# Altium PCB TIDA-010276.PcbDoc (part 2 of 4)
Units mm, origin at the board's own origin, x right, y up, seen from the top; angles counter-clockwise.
Board outline 146.48 x 90.27 mm, 4 copper layers (Top Layer, Signal Layer1, Signal Layer2, Bottom Layer), stack 1.631 mm thick; 271 components, 98 nets, 671 pads, 1828 vias.
Unrouted connection lines stored in the file: 2.
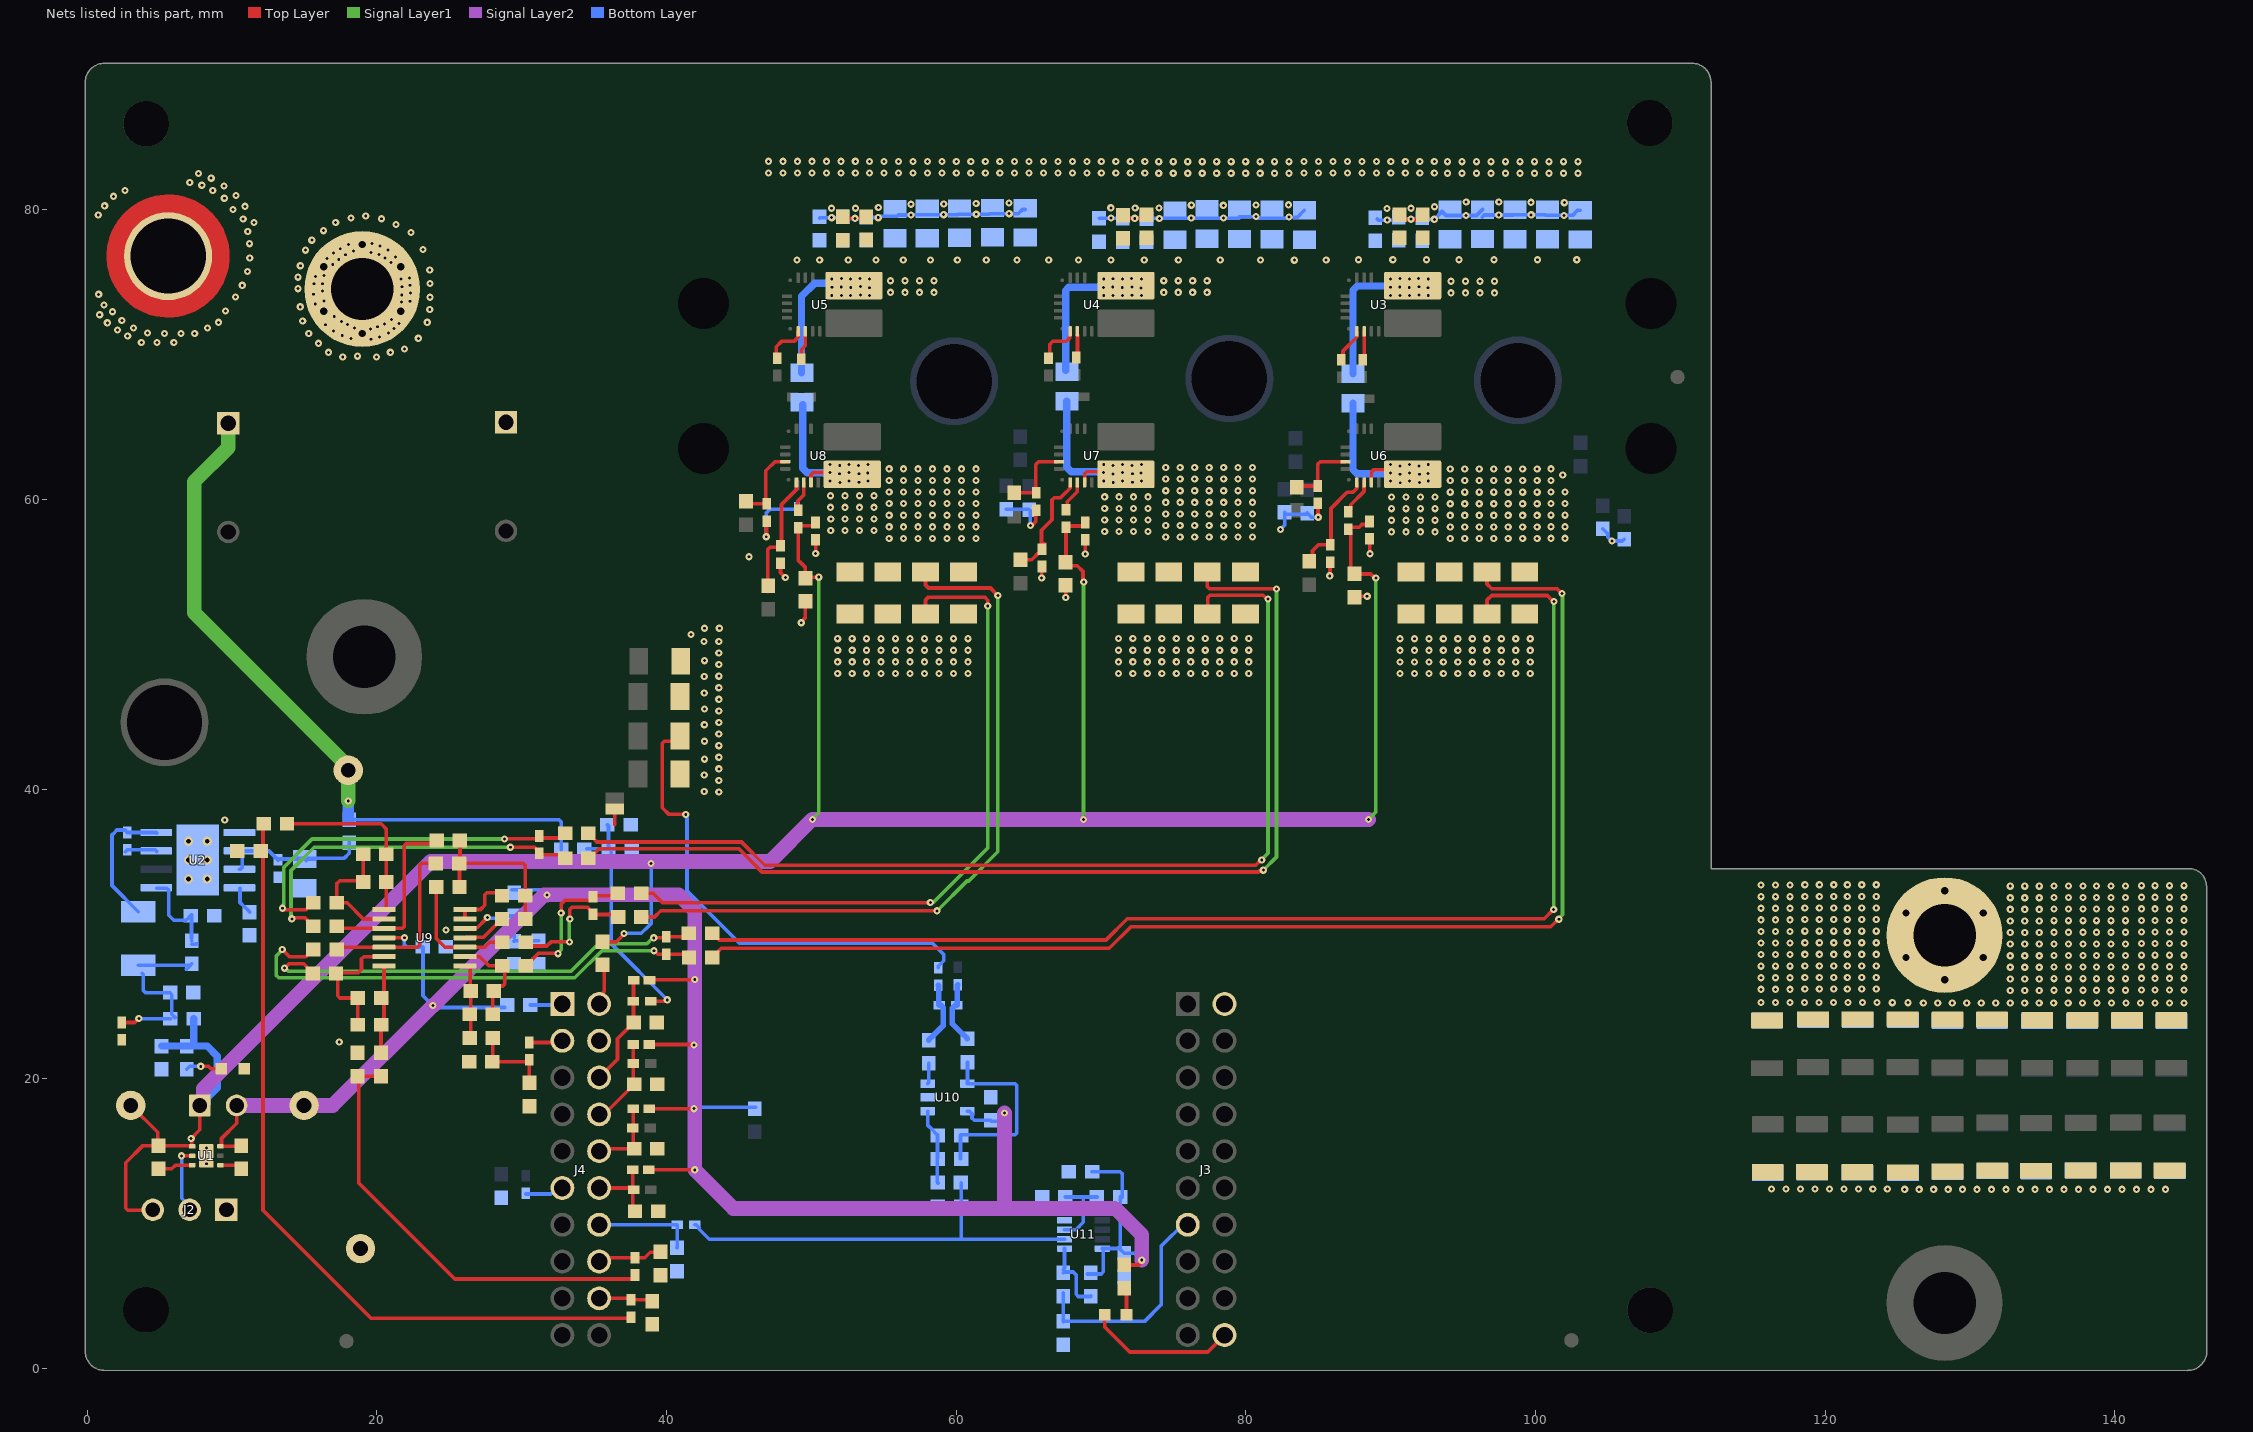
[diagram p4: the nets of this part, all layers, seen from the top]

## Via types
v1: diameter 0.5, hole 0.2, Top Layer to Bottom Layer, tented both sides, 1031 vias
v2: diameter 0.5, hole 0.2, Top Layer to Bottom Layer, 766 vias
v3: diameter 1, hole 0.5, Top Layer to Bottom Layer, 24 vias
v4: diameter 0.63, hole 0.33, Top Layer to Bottom Layer, tented both sides, 6 vias
v5: diameter 1.2, hole 0.8, Top Layer to Bottom Layer, 1 vias

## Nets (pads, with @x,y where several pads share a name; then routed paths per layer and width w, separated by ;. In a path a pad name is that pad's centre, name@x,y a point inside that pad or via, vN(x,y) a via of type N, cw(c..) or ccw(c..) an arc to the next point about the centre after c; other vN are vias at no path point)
"1.65V or 2.5V": C121.1 R46.2 R57.2 R63.2 R79.2 | length 11.3
  Top Layer w0.254: R63.2@25.715,33.294 R57.2@25.715,34.792 ; R57.2@25.732,34.884 25.747,34.899 R46.2@25.747,36.467 ; R57.2@25.77,34.847 25.807,34.884 30.102,34.884 30.251,34.735 R79.2@30.251,32.639 C121.1@30.251,31.042
"3.3V or 5V": C45.1 C104.2 C105.2 C112.2 C114.1 D2.1 D3.1 D4.1 D5.1 J1.2 R58.2 R65.2 R66.2 R78.2 R82.2 R92.1 TP1.1 U1.6 U9.4 U10.5 U11.8 | length 153.2
  Top Layer w0.254: U1.6@9.213,15.34 U1.6@9.265,15.34 ; J1.2@10.329,18.168 10.329,16.93 9.288,15.89 9.288,15.363 U1.6@9.265,15.34 ; C45.1@10.432,15.21 10.303,15.34 U1.6@9.265,15.34 ; U9.4@20.501,29.742 v1(21.911,29.742) ; D5.1@38.78,13.72 v1(41.957,13.72) ; D3.1@38.803,17.944 v1(41.907,17.944) ; D4.1@38.819,22.372 41.879,22.372 v1(41.907,22.345) ; D2.1@38.835,26.815 38.854,26.835 41.942,26.835 v1(41.961,26.854) ; R92.1@71.455,6.993 R92.1@71.617,7.156 72.593,7.156 72.701,7.263 72.701,7.293 72.824,7.416 v1(72.824,7.483)
  Signal Layer2 w0.254: v1(41.957,13.72) v1@41.961,13.725
  Signal Layer2 w1.016: J1.2@10.329,18.168 TP1.1@14.984,18.168 16.975,18.168 23.871,25.065 v1(23.876,25.065) 23.917,25.065 31.553,32.701 v1(31.753,32.701) 31.76,32.708 40.856,32.708 41.961,31.603 v1(41.961,26.854) v1@41.961,13.725 ; v1(41.957,13.72) 44.622,11.055 63.343,11.055 ; v1(63.343,17.64) 63.343,11.055 ; v1(72.824,7.483) 72.824,9.23 70.999,11.055 63.343,11.055
  Bottom Layer w0.254: v1(21.911,29.742) 21.911,29.241 22.06,29.092 23.135,29.092 C104.2@23.167,29.124 23.195,29.096 23.195,25.747 v1(23.876,25.065) ; v1@24.076,24.934 R82.2@28.85,24.934 ; R78.2@29.32,33.055 31.477,33.055 v1@31.626,32.907 ; v1(41.907,17.944) 41.973,17.944 42.066,18.038 R58.2@46.159,18.038 ; 44.383,18.04 R58.2@46.095,18.04 ; U10.5@60.786,17.774 60.928,17.774 61.101,17.601 61.101,17.289 61.25,17.14 C105.2@62.387,17.14 62.451,17.076 63.194,17.076 63.343,17.225 v1(63.343,17.64) ; R66.2@69.061,6.528 70.019,6.528 70.168,6.677 70.168,8.209 U11.8@70.09,8.287 71.286,8.287 C112.2@71.327,8.246 ; C114.1@69.391,13.582 71.335,13.582 71.484,13.433 R65.2@71.484,11.846 ; R65.2@71.327,11.846 C112.2@71.327,8.246 ; v1(72.824,7.483) 72.351,7.956 C112.2@71.617,7.956 C112.2@71.327,8.246
3V3Lauchpad: J4.1 R82.1 | length 2.2
  Bottom Layer w0.254: R82.1@30.616,25.099 32.745,25.099 J4.1@32.817,25.171
5V: C43.1 C44.1 C87.1 C88.1 C89.1 C90.1 C91.1 C92.1 J1.1 J2.3 R2.1 R4.2 R13.1 R14.1 R15.1 R81.1 TP3.1 U1.1 | length 193.1
  Top Layer w0.254: TP3.1@3.019,18.168 4.878,16.309 4.878,15.459 C44.1@4.943,15.395 ; J2.3@4.544,10.962 4.507,10.925 2.819,10.925 2.67,11.073 2.67,14.207 3.858,15.395 C44.1@4.943,15.395 ; J1.1@7.789,18.168 7.789,16.49 v1(7.188,15.89) 7.226,15.852 7.226,15.363 7.165,15.363 7.133,15.395 C44.1@4.943,15.395 ; R81.1@35.584,29.466 36.552,29.466 37.069,29.982 v1(37.069,30.046) ; C91.1@49.598,54.567 49.598,55.317 49.267,55.648 49.258,55.648 49.109,55.797 R15.1@49.109,58.063 49.24,58.194 50.129,58.194 50.302,58.367 C92.1@50.302,58.413 ; C91.1@49.682,54.642 v1(50.519,54.642) ; C87.1@67.558,55.682 67.808,55.432 68.361,55.432 68.767,55.027 68.767,54.36 v1(68.814,54.313) ; C87.1@67.571,55.668 67.591,55.688 R14.1@67.591,58.095 ; R14.1@67.663,58.175 C90.1@68.68,58.175 ; v1(68.793,37.917) 68.793,37.985 v1@68.853,38.046 ; C90.1@68.93,58.517 C90.1@69.103,58.69 ; C88.1@88.468,58.352 88.388,58.272 88.025,58.272 87.832,58.079 87.214,58.079 R13.1@87.08,57.944 87.245,57.779 87.245,55.14 87.53,54.855 88.637,54.855 88.918,54.575 v1(88.984,54.575)
  Signal Layer2 w1.016: J1.1@7.639,17.932 8.031,18.324 8.031,19.31 23.73,35.01 47.176,35.01 v1(50.083,37.917) v1(68.793,37.917) v1(88.471,37.917)
  Signal Layer1 w0.254: v1(50.083,37.917) 50.083,37.937 50.519,38.373 v1(50.519,54.642) ; v1(68.793,37.917) 68.803,37.927 68.803,54.303 v1(68.814,54.313) ; v1(88.471,37.917) 88.984,38.43 v1(88.984,54.575)
  Bottom Layer w0.254: C43.1@5.138,22.27 C43.1@5.141,22.267 ; v1@37.084,30.051 38.27,30.051 38.796,30.577 38.945,30.726 v1(38.945,34.879)
  Bottom Layer w0.508: C43.1@5.138,22.267 5.141,22.267 R4.2@6.891,22.267 R4.2@7.281,22.267 ; R2.1@7.36,24.155 7.36,22.346 R4.2@7.281,22.267 ; J1.1@7.789,18.168 9.003,19.382 9.003,21.565 8.301,22.267 R4.2@7.281,22.267
BAT+: C1.1 C2.1 C3.1 C4.1 C5.1 C6.1 C7.1 C8.1 C9.1 C10.1 C11.1 C12.1 C13.1 C14.1 C15.1 C16.1 C17.1 C18.1 C19.1 C20.1 C21.1 C22.1 C23.1 C24.1 C25.1 C26.1 C27.1 C28.1 C29.1 C30.1 C31.1 C32.1 C33.1 C34.1 C35.1 C36.1 C37.1 C38.1 C39.1 C40.2 C41.2 C42.2 C51.1 C52.1 C53.1 C54.1 C55.1 C56.1 C57.1 C58.1 C59.1 C60.1 C61.1 C62.1 C63.1 C64.1 C65.1 C66.1 C67.1 C68.1 C69.1 C70.1 C71.1 C72.1 C73.1 C74.1 C75.1 C76.1 C77.1 C78.1 C79.1 C80.1 C84.1 C85.1 C86.1 MHA1.1 MHA2.1 MP1.1 R1.2 R48.2 TP2.1 U3.7 U4.7 U5.7 | length 76.4
  Signal Layer1 w1: C1.1@9.751,65.261 9.751,64.994 9.743,64.986 9.743,64.165 9.743,63.589 7.398,61.244 7.398,52.194 18.034,41.557 TP2.1@18.034,41.308 v1(18.034,39.187)
  Bottom Layer w0.254: R1.2@18.575,37.892 32.589,37.892 32.738,37.743 R48.2@32.738,35.832 ; C2.1@28.79,65.83 28.79,65.509 C2.1@28.944,65.355 ; C86.1@67.568,68.911 C86.1@67.653,68.826 ; C3.1@143.806,13.631 C3.1@143.877,13.702
  Bottom Layer w0.508: C84.1@49.327,68.757 49.327,74.032 50.24,74.945 51.807,74.945 v2(52.072,74.681) ; C86.1@67.568,68.911 67.568,74.432 67.783,74.646 v2@70.181,74.646 ; 70.551,74.934 v2(70.815,74.67) ; C85.1@87.404,68.688 87.404,74.447 87.701,74.745 v2@90.773,74.745 ; 90.366,74.941 v2(90.631,74.677)
  Bottom Layer w0.8: v1(18.034,39.187) 18.034,38.674 18.035,38.672 18.035,37.97 R1.2@18.11,37.895
  other v1: 125.495,12.376 126.495,12.376 127.495,12.376 128.495,12.376 129.495,12.376 130.495,12.376 131.495,12.376 132.495,12.376 133.495,12.376 134.495,12.376 135.495,12.376 136.495,12.376 137.495,12.376 138.495,12.376 139.495,12.376 140.495,12.376 141.495,12.376 142.495,12.376 143.495,12.376 116.298,12.398 117.298,12.398 118.298,12.398 119.298,12.398 120.298,12.398 121.298,12.398 122.298,12.398 123.298,12.398 124.298,12.398 126.781,25.248 127.781,25.248 128.781,25.248 129.781,25.248 130.781,25.248 131.781,25.248 132.781,25.248 133.781,25.248 134.781,25.248 135.78,25.248 136.78,25.248 137.78,25.248 138.78,25.248 139.78,25.248 140.78,25.248 141.78,25.248 142.78,25.248 143.78,25.248 144.78,25.248 115.583,25.269 116.583,25.269 117.583,25.269 118.583,25.269 119.583,25.269 120.583,25.269 121.583,25.269 122.583,25.269 123.583,25.269 124.641,25.261 125.722,25.262 132.784,26.105 133.784,26.105 134.784,26.105 135.802,26.123 136.802,26.123 137.802,26.123 138.735,26.123 139.735,26.123 140.735,26.123 141.846,26.143 142.78,26.143 143.78,26.143 144.78,26.143 115.583,26.184 116.583,26.184 117.583,26.184 118.601,26.201 119.601,26.201 120.601,26.201 121.534,26.201 122.534,26.201 123.534,26.201 132.784,26.905 133.784,26.905 134.784,26.905 135.802,26.923 136.802,26.923 137.802,26.923 138.735,26.923 139.735,26.923 140.735,26.923 141.846,26.943 142.78,26.943 143.78,26.943 144.78,26.943 115.583,26.984 116.583,26.984 117.583,26.984 118.601,27.001 119.601,27.001 120.601,27.001 121.534,27.001 122.534,27.001 123.534,27.001 132.784,27.705 133.784,27.705 134.784,27.705 135.802,27.723 136.802,27.723 137.802,27.723 138.735,27.723 139.735,27.723 140.735,27.723 141.846,27.743 142.78,27.743 143.78,27.743 144.78,27.743 115.583,27.784 116.583,27.784 117.583,27.784 118.601,27.801 119.601,27.801 120.601,27.801 121.534,27.801 122.534,27.801 123.534,27.801 132.784,28.505 133.784,28.505 134.784,28.505 135.802,28.523 136.802,28.523 137.802,28.523 138.735,28.523 139.735,28.523 140.735,28.523 141.846,28.543 142.78,28.543 143.78,28.543 144.78,28.543 115.583,28.584 116.583,28.584 117.583,28.584 118.601,28.601 119.601,28.601 120.601,28.601 121.534,28.601 122.534,28.601 123.534,28.601 132.784,29.305 133.784,29.305 134.784,29.305 135.802,29.323 136.802,29.323 137.802,29.323 138.735,29.323 139.735,29.323 140.735,29.323 141.846,29.343 142.78,29.343 143.78,29.343 144.78,29.343 115.583,29.384 116.583,29.384 117.583,29.384 118.601,29.401 119.601,29.401 120.601,29.401 121.534,29.401 122.534,29.401 123.534,29.401 132.784,30.105 133.784,30.105 134.784,30.105 135.802,30.123 136.802,30.123 137.802,30.123 138.735,30.123 139.735,30.123 140.735,30.123 141.846,30.143 142.78,30.143 143.78,30.143 144.78,30.143 115.583,30.184 116.583,30.184 117.583,30.184 118.601,30.201 119.601,30.201 120.601,30.201 121.534,30.201 122.534,30.201 123.534,30.201 132.784,30.905 133.784,30.905 134.784,30.905 135.802,30.923 136.802,30.923 137.802,30.923 138.735,30.923 139.735,30.923 140.735,30.923 141.846,30.943 142.78,30.943 143.78,30.943 144.78,30.943 115.583,30.984 116.583,30.984 117.583,30.984 118.601,31.001 119.601,31.001 120.601,31.001 121.534,31.001 122.534,31.001 123.534,31.001 132.784,31.705 133.784,31.705 134.784,31.705 135.802,31.723 136.802,31.723 137.802,31.723 138.735,31.723 139.735,31.723 140.735,31.723 141.846,31.743 142.78,31.743 143.78,31.743 144.78,31.743 115.583,31.784 116.583,31.784 117.583,31.784 118.601,31.801 119.601,31.801 120.601,31.801 121.534,31.801 122.534,31.801 123.534,31.801 132.784,32.505 133.784,32.505 134.784,32.505 135.802,32.523 136.802,32.523 137.802,32.523 138.735,32.523 139.735,32.523 140.735,32.523 141.846,32.543 142.78,32.543 143.78,32.543 144.78,32.543 115.583,32.584 116.583,32.584 117.583,32.584 118.601,32.601 119.601,32.601 120.601,32.601 121.534,32.601 122.534,32.601 123.534,32.601 132.784,33.305 133.784,33.305 134.784,33.305 135.802,33.323 136.802,33.323 137.802,33.323 138.735,33.323 139.735,33.323 140.735,33.323 141.846,33.343 142.78,33.343 143.78,33.343 144.78,33.343 115.583,33.384 116.583,33.384 117.583,33.384 118.601,33.401 119.601,33.401 120.601,33.401 121.534,33.401 122.534,33.401 123.534,33.401 17.653,69.85 19.99,69.834 18.669,69.901 16.677,70.165 20.942,70.165 21.911,70.386 15.986,70.783 3.749,70.835 4.824,70.835 5.993,70.835 19.606,71.065 18.214,71.128 22.875,71.132 20.205,71.231 2.804,71.283 17.619,71.319 5.351,71.455 6.483,71.455 7.43,71.455 15.308,71.455 4.178,71.5 20.801,71.511 17.027,71.649 2.108,71.701 19.564,71.763 21.19,71.799 3.213,71.847 8.321,71.847 18.468,71.854 20.048,71.934 16.476,72.065 17.993,72.083 20.544,72.115 21.54,72.149 1.401,72.201 9.083,72.236 23.487,72.236 17.562,72.299 14.887,72.333 2.402,72.366 21.021,72.425 17.067,72.648 0.872,72.759 1.766,72.964 9.554,73.026 23.663,73.121 14.719,73.305 1.166,73.428 15.754,73.5 21.701,73.634 22.297,73.692 16.362,73.703 23.682,73.966 10.248,73.985 51.42,74.076 52.72,74.076 54.02,74.076 70.2,74.076 71.5,74.076 72.8,74.076 90,74.076 91.3,74.076 92.6,74.076 21.726,74.119 0.803,74.168 15.628,74.176 22.345,74.269 16.246,74.388 14.569,74.56 21.759,74.692 10.717,74.788 22.307,74.798 15.657,74.899 16.246,74.899 23.682,74.916 51.42,75.216 52.72,75.216 54.02,75.216 70.2,75.216 71.5,75.216 72.8,75.216 90,75.216 91.3,75.216 92.6,75.216 21.688,75.225 22.255,75.292 14.569,75.353 15.783,75.41 16.37,75.455 11.081,75.751 23.663,75.842 14.727,76.144 16.962,76.229 20.976,76.379 17.381,76.584 16.556,76.647 11.232,76.685 20.582,76.677 21.296,76.735 17.842,76.904 20.149,76.908 17.008,77.011 19.601,77.052 18.407,77.157 15.088,77.216 20.784,77.215 23.194,77.261 17.485,77.314 20.236,77.504 18.058,77.613 11.217,77.665 19.678,77.677 15.519,77.906 22.374,78.435 11.097,78.509 16.319,78.564 21.336,78.986 11.528,79.122 17.167,79.129 10.78,79.368 20.327,79.387 18.221,79.442 19.244,79.568 0.773,79.64 10.087,80.032 10.902,80.243 1.218,80.276 9.482,80.799 1.827,80.932 10.277,80.984 2.627,81.344 8.678,81.344 9.449,81.639 7.929,81.7 7.094,81.884 8.572,82.19 7.701,82.509
  other v2: 52.085,74.09 70.828,74.079 90.644,74.086 53.398,74.116 72.141,74.105 91.957,74.112 94.175,74.273 95.175,74.273 96.175,74.273 97.175,74.273 55.471,74.304 56.471,74.304 57.471,74.304 58.471,74.304 74.337,74.306 75.337,74.306 76.337,74.306 77.337,74.306 54.029,74.624 72.772,74.613 92.588,74.62 52.733,74.645 70.17,74.648 71.476,74.634 89.986,74.655 91.292,74.641 51.427,74.658 53.391,74.699 72.134,74.688 91.95,74.695 94.175,75.073 95.175,75.073 96.175,75.073 97.175,75.073 55.471,75.104 56.471,75.104 57.471,75.104 58.471,75.104 74.337,75.106 75.337,75.106 76.337,75.106 77.337,75.106 52.079,75.256 53.373,75.26 70.822,75.245 72.116,75.249 90.638,75.252 91.932,75.256 49.013,76.535 50.583,76.535 52.556,76.535 54.477,76.535 56.357,76.535 58.238,76.535 60.089,76.535 62.082,76.535 64.205,76.535 75.346,76.532 78.24,76.532 81.02,76.532 83.356,76.528 85.552,76.532 66.398,76.547 68.462,76.547 70.705,76.547 72.997,76.547 87.792,76.555 90.155,76.555 92.477,76.555 94.726,76.555 97.142,76.555 100.141,76.555 102.854,76.555 73.994,82.529 74.994,82.529 75.994,82.529 76.994,82.529 77.994,82.529 78.994,82.529 79.994,82.529 80.994,82.529 81.994,82.529 82.994,82.529 93.938,82.529 94.938,82.529 95.938,82.529 96.938,82.529 97.938,82.529 98.938,82.529 99.938,82.529 100.938,82.529 101.938,82.529 102.938,82.529 47.048,82.552 48.048,82.552 49.048,82.552 50.048,82.552 51.048,82.552 52.048,82.552 53.048,82.552 54.021,82.541 55.021,82.541 56.021,82.541 57.021,82.541 58.021,82.541 59.021,82.541 60.021,82.541 61.021,82.541 62.021,82.541 63.021,82.541 64.032,82.541 65.032,82.541 66.032,82.541 67.032,82.541 68.032,82.541 69.032,82.541 70.032,82.541 71.032,82.541 72.032,82.541 73.032,82.541 84.019,82.541 85.019,82.541 86.019,82.541 87.019,82.541 88.019,82.541 89.019,82.541 90.019,82.541 91.019,82.541 92.019,82.541 93.019,82.541 54.021,83.341 55.021,83.341 56.021,83.341 57.021,83.341 58.021,83.341 59.021,83.341 60.021,83.341 61.021,83.341 62.021,83.341 63.021,83.341 64.032,83.341 65.032,83.341 66.032,83.341 67.032,83.341 68.032,83.341 69.032,83.341 70.032,83.341 71.032,83.341 72.032,83.341 73.032,83.341 73.994,83.329 74.994,83.329 75.994,83.329 76.994,83.329 77.994,83.329 78.994,83.329 79.994,83.329 80.994,83.329 81.994,83.329 82.994,83.329 84.019,83.341 85.019,83.341 86.019,83.341 87.019,83.341 88.019,83.341 89.019,83.341 90.019,83.341 91.019,83.341 92.019,83.341 93.019,83.341 93.938,83.329 94.938,83.329 95.938,83.329 96.938,83.329 97.938,83.329 98.938,83.329 99.938,83.329 100.938,83.329 101.938,83.329 102.938,83.329 47.048,83.352 48.048,83.352 49.048,83.352 50.048,83.352 51.048,83.352 52.048,83.352 53.048,83.352
  other v3: 128.254,26.846 125.591,28.384 130.917,28.384 125.591,31.458 130.917,31.458 128.254,32.996 19.001,71.455 16.338,72.993 21.664,72.993 16.338,76.067 21.664,76.067 19.001,77.605
DCBUS: C107.1 R48.1 R52.2 R84.1 | length 16.6
  Top Layer w0.254: R84.1@38.925,25.365 39.902,25.365 39.994,25.458 v1(40.063,25.458)
  Bottom Layer w0.254: R48.1@34.509,35.9 36.003,35.9 36.185,35.9 36.203,35.882 36.203,29.318 v1(40.063,25.458) ; C107.1@35.934,37.546 36.003,37.477 R52.2@36.003,35.882
GaN_U_AGND: C51.2 C52.2 C53.2 C54.2 C55.2 C66.2 C69.2 C70.2 C71.2 C72.2 C85.2 R22.1 R25.2 R26.2 R27.2 R28.2 U6.4 U6.6 | length 115.1
  Top Layer w0.254: R22.1@43.161,28.384 43.186,28.384 43.534,28.732 43.534,28.757 43.791,29.014 70.583,29.014 72.078,30.509 101.061,30.509 101.574,31.023 v1(101.619,31.023) ; U6.4@88.675,61.187 88.675,61.899 88.824,62.048 U6.6@91.214,62.048 ; C69.2@90.624,79.34 90.63,79.333 C72.2@92.187,79.333 ; R25.2@96.656,54.593 96.656,54.172 96.991,53.837 101.496,53.837 v1(101.827,53.507)
  Signal Layer1 w0.254: v1(101.619,31.023) 101.619,31.089 101.869,31.34 101.869,53.465 v1(101.827,53.507)
  Bottom Layer w0.254: C71.2@89.073,79.364 89.146,79.291 v1(89.772,79.291) 90.557,79.291 90.63,79.364 92.186,79.364 92.202,79.348 v1(93.019,79.348) 93.556,79.885 93.834,79.607 95.929,79.607 C55.2@96.343,80.021 ; C55.2@96.337,79.502 96.337,79.513 96.463,79.64 98.452,79.64 98.47,79.657 v1(99.706,79.657) 100.675,79.657 100.714,79.617 102.561,79.617 102.927,79.984 C54.2@103.092,79.984
  Bottom Layer w0.508: C85.2@87.404,66.656 87.404,62.068 87.701,61.771 v2@89.99,61.771
  other v1: 90,61.287 91.3,61.287 92.6,61.287 90,62.427 91.3,62.427 92.6,62.427 91.409,79.36 95.204,79.607 101.973,79.617 97.468,79.64 89.745,80.095 91.416,80.112 93.039,80.218 101.997,80.495 99.7,80.521 95.218,80.539 97.472,80.539
  other v2: 94.121,57.308 95.121,57.308 96.121,57.308 97.121,57.308 98.121,57.308 99.121,57.308 100.121,57.308 101.085,57.32 102.041,57.32 90.062,57.769 91.062,57.769 92.062,57.769 93.062,57.769 94.121,58.108 95.121,58.108 96.121,58.108 97.121,58.108 98.121,58.108 99.121,58.108 100.121,58.108 101.085,58.12 102.041,58.12 90.062,58.569 91.062,58.569 92.062,58.569 93.062,58.569 94.121,58.908 95.121,58.908 96.121,58.908 97.121,58.908 98.121,58.908 99.121,58.908 100.121,58.908 101.085,58.92 102.041,58.92 90.062,59.369 91.062,59.369 92.062,59.369 93.062,59.369 94.121,59.708 95.121,59.708 96.121,59.708 97.121,59.708 98.121,59.708 99.121,59.708 100.121,59.708 101.085,59.72 102.041,59.72 90.062,60.169 91.062,60.169 92.062,60.169 93.062,60.169 94.121,60.508 95.121,60.508 96.121,60.508 97.121,60.508 98.121,60.508 99.121,60.508 100.121,60.508 101.085,60.52 102.041,60.52 90.665,61.156 91.993,61.166 94.121,61.308 95.121,61.308 96.121,61.308 97.121,61.308 98.121,61.308 99.121,61.308 100.121,61.308 101.085,61.32 101.884,61.697 90.651,61.747 91.986,61.749 92.591,61.811 89.989,61.845 91.295,61.832 94.121,62.108 95.121,62.108 96.121,62.108 97.121,62.108 98.121,62.108 99.121,62.108 100.121,62.108 101.085,62.12 91.968,62.31 90.658,62.323
GaN_V_AGND: C56.2 C57.2 C58.2 C59.2 C60.2 C67.2 C73.2 C74.2 C75.2 C76.2 C86.2 R23.1 R29.2 R30.2 R31.2 R32.2 U7.4 U7.6 | length 99.6
  Top Layer w0.254: R23.1@34.639,35.175 34.664,35.175 35.012,35.523 35.012,35.548 35.346,35.882 45.011,35.882 46.603,34.29 80.875,34.29 80.949,34.364 81.17,34.364 v1(81.217,34.411) ; U7.4@68.875,61.187 68.875,61.773 69.024,61.922 U7.6@71.54,61.922 ; C74.2@71.526,79.64 71.75,79.417 v1(72.337,79.417) ; C74.2@71.529,79.403 C74.2@71.532,79.405 ; v1@72.292,79.425 72.3,79.417 72.901,79.417 C73.2@73.157,79.672 ; R31.2@77.343,55.008 77.343,53.995 77.491,53.846 82.094,53.846 v1(82.121,53.819)
  Signal Layer1 w0.254: v1(81.217,34.411) 82.121,35.316 v1(82.121,53.819)
  Bottom Layer w0.254: C75.2@69.894,79.425 C60.2@79.557,79.425 ; C60.2@79.574,79.516 v1@80.7,79.516 ; v1@80.682,79.425 v1@82.946,79.425 ; v1@82.99,79.481 83.555,79.481 C59.2@84.048,79.974
  Bottom Layer w0.508: C86.2@67.653,66.794 67.653,62.219 67.951,61.922 69.755,61.922
  other v1: 70.2,61.287 71.5,61.287 72.8,61.287 70.2,62.427 71.5,62.427 72.8,62.427 74.033,79.41 70.69,79.445 76.24,79.438 78.461,79.445 82.99,79.508 80.7,79.536 70.688,80.141 72.367,80.12 74.011,80.134 78.453,80.311 76.242,80.325 80.713,80.333 82.952,80.347
  other v2: 74.474,57.409 75.474,57.409 76.474,57.409 77.474,57.409 78.474,57.409 79.474,57.409 80.474,57.409 70.258,57.789 71.258,57.789 72.258,57.789 73.258,57.789 74.474,58.209 75.474,58.209 76.474,58.209 77.474,58.209 78.474,58.209 79.474,58.209 80.474,58.209 70.258,58.589 71.258,58.589 72.258,58.589 73.258,58.589 74.474,59.009 75.474,59.009 76.474,59.009 77.474,59.009 78.474,59.009 79.474,59.009 80.474,59.009 70.258,59.389 71.258,59.389 72.258,59.389 73.258,59.389 74.474,59.809 75.474,59.809 76.474,59.809 77.474,59.809 78.474,59.809 79.474,59.809 80.474,59.809 70.258,60.189 71.258,60.189 72.258,60.189 73.258,60.189 74.474,60.609 75.474,60.609 76.474,60.609 77.474,60.609 78.474,60.609 79.474,60.609 80.474,60.609 70.855,61.186 72.184,61.196 74.474,61.409 75.474,61.409 76.474,61.409 77.474,61.409 78.474,61.409 79.474,61.409 80.474,61.409 70.842,61.776 72.176,61.778 72.782,61.841 70.18,61.875 71.486,61.861 74.474,62.209 75.474,62.209 76.474,62.209 77.474,62.209 78.474,62.209 79.474,62.209 80.474,62.209 70.849,62.352 72.159,62.34
GaN_W_AGND: C61.2 C62.2 C63.2 C64.2 C65.2 C68.2 C77.2 C78.2 C79.2 C80.2 C84.2 R24.1 R33.2 R34.2 R35.2 R36.2 U8.4 U8.6 | length 75.5
  Top Layer w0.254: R24.1@38.277,31.176 39.188,31.176 39.615,31.603 58.691,31.603 v1(58.693,31.605) ; U8.4@49.984,61.187 49.984,61.713 50.139,61.867 U8.6@51.314,61.867 ; C77.2@52.176,79.511 52.27,79.416 v1(53.029,79.416) 53.7,79.416 C78.2@53.807,79.524 ; R35.2@57.89,55.008 57.89,54.101 58.101,53.89 62.372,53.89 v1(62.884,53.378)
  Signal Layer1 w0.254: v1(58.693,31.605) 60.754,33.667 60.87,33.667 62.884,35.681 v1(62.884,53.378)
  Bottom Layer w0.254: C79.2@50.595,79.444 50.614,79.463 v1(51.41,79.463) 52.134,79.463 52.202,79.396 C68.2@53.794,79.396 ; C68.2@53.805,79.468 v1@54.627,79.468 ; v1@54.63,79.409 54.643,79.409 54.788,79.554 55.919,79.554 56.008,79.644 56.962,79.644 56.975,79.657 59.132,79.657 v1(59.145,79.67) 60.1,79.67 60.126,79.696 62.298,79.696 62.338,79.736 64.301,79.736 64.59,80.025 C65.2@64.755,80.025
  Bottom Layer w0.508: C84.2@49.417,66.545 49.417,62.167 49.722,61.862 v2@51.961,61.862
  other v1: 51.309,61.287 52.609,61.287 53.909,61.287 51.309,62.427 52.609,62.427 53.909,62.427 54.627,79.46 56.896,79.644 61.394,79.696 63.666,79.736 51.409,80.113 53.065,80.112 54.635,80.17 56.896,80.386 59.151,80.402 61.386,80.444 63.662,80.465
  other v2: 55.38,57.318 56.38,57.318 57.38,57.318 58.38,57.318 59.38,57.318 60.38,57.318 61.38,57.318 51.351,57.858 52.326,57.861 53.326,57.861 54.326,57.861 55.38,58.118 56.38,58.118 57.38,58.118 58.38,58.118 59.38,58.118 60.38,58.118 61.38,58.118 51.355,58.663 52.326,58.661 53.326,58.661 54.326,58.661 55.38,58.918 56.38,58.918 57.38,58.918 58.38,58.918 59.38,58.918 60.38,58.918 61.38,58.918 51.326,59.461 52.326,59.461 53.326,59.461 54.326,59.461 55.38,59.718 56.38,59.718 57.38,59.718 58.38,59.718 59.38,59.718 60.38,59.718 61.38,59.718 51.326,60.261 52.326,60.261 53.326,60.261 54.326,60.261 55.38,60.518 56.38,60.518 57.38,60.518 58.38,60.518 59.38,60.518 60.38,60.518 61.38,60.518 51.974,61.187 53.303,61.197 55.38,61.318 56.38,61.318 57.38,61.318 58.38,61.318 59.38,61.318 60.38,61.318 61.38,61.318 51.961,61.778 53.296,61.78 53.901,61.842 51.299,61.876 52.605,61.863 55.38,62.118 56.38,62.118 57.38,62.118 58.38,62.118 59.38,62.118 60.38,62.118 61.38,62.118 51.968,62.354 53.278,62.341
GND: C43.2 C44.2 C45.2 C47.2 C48.2 C49.2 C50.2 C87.2 C88.2 C89.2 C90.2 C91.2 C92.2 C93.2 C94.2 C95.2 C96.2 C97.2 C98.2 C104.1 C105.1 C106.2 C107.2 C109.2 C110.2 C112.1 C113.2 C114.2 C115.2 C117.2 C118.2 C119.2 C120.2 C121.2 C122.2 C123.2 C124.2 C125.2 C126.2 C127.2 C128.2 C129.2 C130.2 D1.1 J2.1 J3.2 J4.4 NT1.2 R5.1 R6.1 R52.1 R70.1 R75.1 R76.1 R77.1 R80.1 RT1.1 TP4.1 U1.3 U1.4 U1.7@8.238,14.69 U2.1 U2.9 U9.11 U10.2 U11.4 | length 33.5
  Top Layer w0.254: C44.2@4.943,13.795 5.855,13.795 6.1,14.04 U1.3@7.263,14.04 ; U1.4@9.213,14.04 10.404,14.04 C45.2@10.648,13.795 ; U9.11@26.101,29.742 26.149,29.79 27.399,29.79 28.278,30.669 28.278,30.694 28.626,31.042 C121.2@28.651,31.042 ; 36.437,37.549 36.443,37.555 NT1.2@36.443,38.632 ; C95.2@46.856,58.504 C95.2@46.889,58.471 ; v1(46.895,57.434) 46.911,57.45 46.911,58.488 C95.2@46.927,58.504 ; C98.2@47.879,55.597 47.879,54.95 v1(48.212,54.618) ; v1(49.309,51.495) 49.309,51.561 49.598,51.85 C91.2@49.598,52.967 ; C92.2@50.302,57.213 50.326,57.188 50.306,57.168 50.306,56.272 v1(50.309,56.269) ; v1(65.133,58.203) 65.18,58.25 65.274,58.25 65.51,58.486 65.51,59.241 C94.2@65.536,59.267 ; v1(65.91,54.589) 65.923,54.602 65.923,55.365 C97.2@65.935,55.378 ; C87.2@67.558,54.082 67.571,54.069 v1(67.571,53.242) ; v1(68.923,56.247) 68.93,56.254 C90.2@68.93,57.217 ; C93.2@84.977,59.735 84.991,59.721 84.991,58.794 v1(85.005,58.779) ; C96.2@85.678,55.695 85.678,55.678 C96.2@85.766,55.591 ; v1(85.797,54.734) 85.82,54.756 85.82,55.646 C96.2@85.843,55.668 ; C89.2@87.517,53.269 87.575,53.326 v1(88.381,53.326) ; C88.2@88.544,57.284 88.559,57.268 88.559,56.274 v1(88.574,56.258)
  Bottom Layer w0.254: v1(46.895,57.434) 46.895,59.072 47.158,59.335 48.946,59.335 49.023,59.411 RT1.1@49.023,59.699 ; C119.2@63.473,59.338 65.025,59.338 R77.1@65.061,59.302 65.133,59.23 v1(65.133,58.203) ; v1(82.404,57.924) 82.404,57.947 82.684,58.226 C118.2@82.684,59.107 ; C118.2@82.8,58.991 84.173,58.991 R76.1@84.252,59.069 84.541,58.779 v1(85.005,58.779) v1@85.01,58.775 ; C117.2@104.643,57.979 104.991,57.631 104.991,57.406 v1@105.262,57.134 ; v1(105.289,57.134) v1@105.262,57.134 ; R75.1@106.129,57.26 106.004,57.134 v1@105.262,57.134
  other v1: 17.414,22.553 24.793,30.272 9.507,37.878 45.712,56.053
  other v2: 8.238,14.14 8.238,15.24
  other v4: 7.002,33.809 8.302,33.809 7.002,35.109 8.302,35.109 7.002,36.409 8.302,36.409
I_Bus_N: C102.2 R45.1 R53.1 | length 4.3
  Bottom Layer w0.381: C102.2@59.946,25.084 59.744,24.881 59.744,23.8 60.476,23.068 60.501,23.068 60.786,22.784 R53.1@60.786,22.759 ; C102.2@60.046,25.084 60.082,25.119 60.082,26.461 R45.1@60.117,26.496
I_Bus_P: C102.1 R40.1 R56.1 | length 4.4
  Bottom Layer w0.381: R56.1@58.108,22.67 58.108,22.695 58.393,22.979 58.418,22.979 59.109,23.671 59.109,24.921 58.946,25.084 C102.1@58.846,25.084 58.805,25.126 58.805,26.437 R40.1@58.763,26.479
I_U_N: C99.2 R37.2 R61.2 | length 31.2
  Top Layer w0.254: v1(13.634,27.643) 13.943,27.952 14.958,27.952 15.208,27.702 15.208,27.677 15.556,27.329 R61.2@15.581,27.329 ; v1(39.127,29.74) C99.2@39.813,29.74 ; C99.2@39.986,29.814 41.309,29.814 R37.2@41.554,30.059
  Signal Layer1 w0.254: v1(13.634,27.643) 13.698,27.643 13.906,27.436 33.419,27.436 35.317,29.334 38.654,29.334 39.06,29.74 v1(39.127,29.74)
I_U_P: C99.1 R22.2 R60.1 | length 34.1
  Top Layer w0.254: v1(13.476,28.942) 13.984,28.434 15.11,28.434 15.259,28.583 15.259,28.594 15.607,28.942 R60.1@15.632,28.942 ; v1(39.139,28.848) 39.152,28.848 39.402,28.598 39.971,28.598 C99.1@39.986,28.614 41.332,28.614 R22.2@41.561,28.384
  Signal Layer1 w0.254: v1(13.476,28.942) 13.476,28.894 13.054,28.472 13.054,27.16 13.236,26.978 33.68,26.978 35.549,28.848 v1(39.139,28.848)
I_V_N: C100.2 R38.2 R51.1 | length 25.6
  Top Layer w0.254: v1(13.491,31.783) 13.558,31.783 13.667,31.673 15.116,31.673 15.607,32.164 R51.1@15.632,32.164 ; v1@28.83,36.576 31.039,36.576 31.212,36.749 C100.2@31.212,36.773 ; C100.2@31.212,36.63 R38.2@33.013,36.63
  Signal Layer1 w0.254: v1(13.491,31.783) 13.538,31.83 13.538,32 13.593,32.055 13.593,34.619 15.541,36.568 28.822,36.568 v1(28.825,36.571)
I_V_P: C100.1 R23.2 R50.1 | length 25.1
  Top Layer w0.254: v1(14.141,31.051) 14.208,31.051 14.276,31.119 15.055,31.119 15.259,30.915 15.259,30.89 15.607,30.542 R50.1@15.632,30.542 ; v1(29.226,35.99) 30.895,35.99 31.212,35.673 C100.1@31.212,35.573 31.312,35.473 32.742,35.473 R23.2@33.039,35.175
  Signal Layer1 w0.254: v1(14.141,31.051) 14.094,31.098 14.094,31.272 14.088,31.278 14.088,34.388 15.69,35.99 v1(29.226,35.99)
I_W_N: C101.2 R39.2 R68.1 | length 10.4
  Top Layer w0.254: R68.1@30.284,27.804 30.309,27.804 31.173,28.669 32.489,28.669 v1(32.509,28.649) ; v1(32.738,31.447) 32.742,31.451 32.742,32.078 33.006,32.341 34.757,32.341 34.93,32.514 C101.2@34.93,32.58 34.993,32.643 36.478,32.643 R39.2@36.651,32.816
  Signal Layer1 w0.254: v1(32.509,28.649) 32.509,28.692 32.738,28.921 v1(32.738,31.447)
I_W_P: C101.1 R24.2 R64.1 | length 9.2
  Top Layer w0.254: R64.1@30.284,29.429 30.542,29.171 31.743,29.171 32.033,29.46 v1(33.318,29.46) ; v1(33.335,31.046) 33.335,31.701 33.484,31.85 34.56,31.85 34.93,31.48 C101.1@34.93,31.38 ; C101.1@34.93,31.349 36.504,31.349 R24.2@36.677,31.176
  Signal Layer1 w0.254: v1(33.318,29.46) 33.302,29.476 33.302,31.012 v1(33.335,31.046)
IBUS: C109.1 R55.2 R89.1 U11.2 | length 29.7
  Bottom Layer w0.254: R89.1@41.957,9.931 42.057,9.931 42.23,9.758 42.23,9.658 42.951,8.937 60.351,8.937 ; C109.1@60.351,11.194 60.351,8.937 ; C109.1@60.351,11.338 R55.2@60.351,12.813 ; U11.2@67.49,8.937 60.351,8.937
IU: C110.1 R59.2 R90.1 | length 30.9
  Top Layer w0.254: C110.1@18.681,20.195 18.752,20.124 18.752,12.815 25.384,6.183 37.565,6.183 R90.1@37.84,6.458 ; C110.1@18.778,20.192 R59.2@20.289,20.192
IV: C106.1 R49.2 R91.1 | length 55
  Top Layer w0.254: R49.2@12.15,37.381 12.15,35.884 12.15,10.925 19.608,3.467 37.471,3.467 R91.1@37.56,3.555
IW: C113.1 C122.1 R67.2 R83.2 | length 5.8
  Top Layer w0.254: R67.2@28.023,22.816 28.023,21.22 C113.1@27.98,21.177 30.353,21.177 R83.2@30.508,21.332 ; R83.2@30.526,21.315 30.526,19.754 C122.1@30.554,19.725
NetC46_1: C46.1 U2.7 | length 2.3
  Bottom Layer w0.254: C46.1@2.642,35.672 C46.1@2.784,35.814 4.707,35.814 U2.7@4.817,35.704
NetC46_2: C46.2 L1.1 U2.8 | length 9.4
  Bottom Layer w0.254: L1.1@3.544,31.539 1.729,33.354 1.729,36.841 1.907,37.019 1.907,37.036 2.056,37.184 2.614,37.184 C46.2@2.784,37.014 U2.8@4.777,37.014 U2.8@4.817,36.974
NetC47_1: C47.1 C48.1 R1.1 U2.2 U2.3 | length 11.4
  Bottom Layer w0.254: U2.3@10.527,34.474 10.593,34.474 10.716,34.597 10.716,35.621 10.593,35.744 U2.2@10.527,35.744 ; U2.2@10.851,35.739 12.568,35.739 C48.1@13.188,35.119 ; C48.1@13.188,35.178 C47.1@15.234,35.178 ; C47.1@14.505,35.178 14.57,35.243 17.77,35.243 18.102,35.575 R1.1@18.102,36.396 ; C47.1@15.125,35.069 C47.1@15.234,35.178 ; C47.1@15.764,35.178 C47.1@15.234,35.178
NetC49_1: C49.1 C50.1 L1.2 R2.2 R3.2 | length 12.4
  Top Layer w0.254: C50.1@2.396,23.893 3.3,23.893 v1(3.578,24.171)
  Bottom Layer w0.254: L1.2@3.544,27.839 R3.2@7.12,27.839 ; v1(3.578,24.171) 3.594,24.155 R2.2@5.76,24.155 R2.2@5.785,24.155 ; L1.2@3.819,27.278 3.881,27.216 3.881,26.107 4.03,25.958 C49.1@5.745,25.958 ; C49.1@5.858,25.82 5.858,24.457 R2.2@6.077,24.237 ; R3.2@6.855,27.573 6.88,27.573 7.12,27.814 R3.2@7.12,27.839 ; R3.2@7.228,27.946 R3.2@7.12,27.839
NetC93_1: C93.1 R16.1 U6.14 | length 4.5
  Top Layer w0.254: R16.1@83.898,60.935 C93.1@84.977,60.935 ; C93.1@84.977,61.042 84.977,62.445 85.143,62.612 U6.14@86.9,62.612
NetC94_1: C94.1 R17.1 U7.14 | length 5.1
  Top Layer w0.254: R17.1@63.948,60.469 65.446,60.469 65.5,60.524 65.5,62.412 65.7,62.612 U7.14@67.1,62.612
NetC95_1: C95.1 R18.1 U8.14 | length 5
  Top Layer w0.254: R18.1@45.492,59.867 45.658,59.7 C95.1@46.729,59.7 ; C95.1@46.862,59.899 46.862,61.981 47.493,62.612 U8.14@48.209,62.612
NetC96_1: C96.1 R19.1 U6.2 | length 7.5
  Top Layer w0.254: R19.1@84.508,55.679 84.607,55.778 84.607,56.461 85.014,56.868 C96.1@85.843,56.868 ; C96.1@85.881,56.868 85.881,59.388 87,60.507 87.407,60.507 87.675,60.774 U6.2@87.675,61.187
NetC97_1: C97.1 R20.1 U7.2 | length 7.2
  Top Layer w0.254: R20.1@64.458,55.836 65.226,55.836 65.695,56.305 65.762,56.305 65.935,56.478 C97.1@65.935,56.578 ; C97.1@66.128,56.947 65.895,56.947 65.895,57.876 66.628,58.609 66.628,59.975 66.776,60.123 67.211,60.123 67.595,60.507 67.607,60.507 67.873,60.772 U7.2@67.873,60.964
NetC98_1: C98.1 R21.1 U8.2 | length 8.7
  Top Layer w0.254: R21.1@47.003,53.652 47.003,56.549 47.152,56.697 47.779,56.697 C98.1@47.879,56.797 ; C98.1@47.946,56.797 47.946,59.658 48.984,60.696 U8.2@48.984,61.187
NetC103_1: C103.1 R47.2 R55.1 U10.1 | length 5.3
  Bottom Layer w0.254: U10.1@58.036,17.774 58.036,16.822 58.352,16.506 58.352,16.481 58.7,16.133 58.725,16.133 58.725,14.53 58.705,14.51 58.705,12.859 R55.1@58.751,12.813
NetC103_2: C103.2 R47.1 R53.2 U10.4 | length 13.8
  Bottom Layer w0.254: C103.2@60.305,14.51 60.305,16.113 60.325,16.133 64.052,16.133 64.201,16.282 64.201,19.525 64.052,19.674 U10.4@60.786,19.674 R53.2@60.786,21.159
NetC108_1: C108.1 R49.1 R54.2 U9.1 | length 12.7
  Top Layer w0.254: R49.1@13.806,37.617 20.306,37.617 20.667,37.256 20.667,35.192 C108.1@20.667,33.597 20.667,31.74 20.619,31.692 U9.1@20.501,31.692
NetC108_2: C108.2 R51.2 R54.1 U9.2 | length 8.6
  Top Layer w0.254: R54.1@19.067,35.192 C108.2@19.067,33.597 18.984,33.681 17.457,33.681 17.232,33.456 R51.2@17.232,32.164 17.24,32.157 17.964,32.157 19.079,31.042 U9.2@20.501,31.042
NetC111_1: C111.1 R59.1 R62.2 U9.7 | length 5.6
  Top Layer w0.254: R59.1@20.289,21.792 20.299,21.802 R62.2@20.299,23.984 ; R62.2@20.299,24.002 20.501,24.204 C111.1@20.501,25.585 ; 20.501,26.06 U9.7@20.501,27.792
NetC111_2: C111.2 R61.1 R62.1 U9.6 | length 8.8
  Top Layer w0.254: R61.1@17.181,27.329 17.312,27.329 18.713,27.329 18.949,27.565 18.949,28.293 19.098,28.442 U9.6@20.501,28.442 ; R61.1@17.312,27.249 17.312,25.732 17.461,25.584 17.671,25.584 17.673,25.585 C111.2@18.699,25.585 R62.1@18.699,24.002
NetC116_1: C116.1 R67.1 R74.2 U9.8 | length 5.3
  Top Layer w0.254: U9.8@26.101,27.792 26.403,27.792 26.451,27.744 26.451,26.101 C116.1@26.489,26.063 26.489,22.897 R67.1@26.412,22.819
NetC116_2: C116.2 R68.2 R74.1 U9.9 | length 6.7
  Top Layer w0.254: U9.9@26.101,28.442 27.121,28.442 27.758,27.804 R68.2@28.684,27.804 28.839,27.649 28.839,26.56 28.691,26.411 28.437,26.411 28.022,25.996 R74.1@28.022,24.457
NetC120_1: C120.1 R78.1 R80.2 U9.12 | length 6.8
  Top Layer w0.254: U9.12@26.101,30.392 26.149,30.44 26.947,30.44 v1@27.507,30.999
  Bottom Layer w0.254: v1(27.639,31.15) 27.705,31.084 28.205,31.084 28.368,31.248 29.32,31.248 R78.1@29.491,31.248 C120.1@29.491,29.754 ; C120.1@29.484,29.504 29.513,29.533 R80.2@31.169,29.533
NetC124_1: C124.1 J4.18 R91.2 | length 3.8
  Top Layer w0.254: J4.18@35.357,4.851 37.464,4.851 R91.2@37.56,4.755 38.92,4.755 C124.1@39.025,4.651
NetC125_1: C125.1 J4.16 R90.2 | length 4.5
  Top Layer w0.254: J4.16@35.357,7.391 35.624,7.658 R90.2@37.84,7.658 38.513,7.658 38.881,8.026 39.565,8.026 C125.1@39.588,8.049
NetC126_1: C126.1 J4.14 R89.2 | length 7
  Bottom Layer w0.254: J4.14@35.357,9.931 R89.2@40.757,9.931 40.757,8.355 C126.1@40.735,8.333
NetC127_1: C127.1 D5.2 J4.12 R88.2 | length 5.3
  Top Layer w0.254: J4.12@35.357,12.471 37.617,12.471 R88.2@37.68,12.409 ; D5.2@37.68,13.72 R88.2@37.68,12.409 ; C127.1@37.834,10.863 37.68,11.017 R88.2@37.68,12.409
NetC128_1: C128.1 D3.2 J4.10 R86.2 | length 5.3
  Top Layer w0.254: J4.10@35.357,15.011 35.516,15.17 C128.1@37.784,15.17 37.703,15.251 D3.2@37.703,17.944
NetC129_1: C129.1 D4.2 J4.8 R85.2 | length 6.1
  Top Layer w0.254: J4.8@35.357,17.551 35.709,17.551 37.409,19.251 37.409,19.276 37.757,19.624 C129.1@37.782,19.624 37.719,19.687 D4.2@37.719,22.372
NetC130_1: C130.1 D2.2 J4.6 R84.2 | length 7.7
  Top Layer w0.254: J4.6@35.357,20.091 36.627,21.361 36.627,22.777 37.378,23.528 37.378,23.553 C130.1@37.726,23.901 ; D2.2@37.735,26.815 37.735,23.918 C130.1@37.751,23.901
NetD1_2: D1.2 R4.1 | length 2.5
  Top Layer w0.254: v1(7.853,20.865) 8.389,20.865 8.558,20.696 9.261,20.696 D1.2@9.267,20.702
  Bottom Layer w0.254: R4.1@6.891,20.667 7.09,20.865 v1(7.853,20.865)
NetD6_1: D6.1 R92.2 | length 1.6
  Top Layer w0.254: D6.1@71.768,4.03 R92.2@71.768,5.606
NetD6_2: D6.2 J3.20 | length 10.3
  Top Layer w0.254: D6.2@70.268,3.708 70.268,2.864 71.985,1.147 77.373,1.147 J3.20@78.537,2.311
NetJ2_2: J2.2 U1.2 | length 4.4
  Top Layer w0.254: v1(6.528,14.69) U1.2@7.263,14.69
  Bottom Layer w0.254: J2.2@6.545,11.15 6.79,11.395 6.79,11.514 6.545,11.759 v1@6.545,14.658
NetJ4_2: J4.2 R81.2 | length 3
  Top Layer w0.254: J4.2@35.357,25.171 35.624,25.439 35.624,25.936 35.706,26.018 R81.2@35.706,28.041
NetJ4_3: J4.3 R83.1 | length 2.3
  Top Layer w0.254: R83.1@30.526,22.515 32.7,22.515 J4.3@32.817,22.631
NetJ4_11: J4.11 R87.1 | length 2.7
  Bottom Layer w0.254: R87.1@30.284,12.055 32.023,12.055 32.439,12.471 J4.11@32.817,12.471
NetR3_1: R3.1 R6.2 U2.5 | length 6.5
  Bottom Layer w0.254: U2.5@4.817,33.164 5.511,33.164 5.634,33.041 5.634,31.301 5.979,30.956 6.849,30.956 7.209,31.316 R3.1@7.209,29.704 ; R3.1@7.228,29.296 7.516,29.296 7.544,29.324 R3.1@7.593,29.324 ; R3.1@7.228,29.541 R3.1@7.228,29.546
NetR5_2: R5.2 U2.4 | length 1.9
  Bottom Layer w0.254: U2.4@10.567,33.164 10.567,32.173 10.851,31.889 10.876,31.889 11.224,31.541 R5.2@11.224,31.516
NetR7_2: R7.2 U3.3 | length 2.2
  Top Layer w0.254: R7.2@88.173,69.377 88.173,71.614 U3.3@88.175,71.616
NetR8_2: R8.2 U4.3 | length 1.6
  Top Layer w0.254: R8.2@68.3,69.807 68.387,69.893 68.387,71.383 U4.3@68.377,71.393
NetR9_2: R9.2 U5.3 | length 2
  Top Layer w0.254: R9.2@49.303,69.698 49.327,69.723 49.327,70.348 49.595,70.616 U5.3@49.595,71.616
NetR10_2: R10.2 U3.2 | length 2.4
  Top Layer w0.254: R10.2@86.541,69.643 86.72,69.822 86.72,70.248 87.673,71.201 87.673,71.614 U3.2@87.675,71.616
NetR11_2: R11.2 U4.2 | length 2.8
  Top Layer w0.254: R11.2@66.462,69.965 66.462,70.71 66.682,70.931 67.602,70.931 67.86,71.188 67.86,71.306 67.875,71.322 U4.2@67.875,71.616
NetR12_2: R12.2 U5.2 | length 2.8
  Top Layer w0.254: R12.2@47.582,69.936 47.582,70.057 47.582,70.555 47.946,70.919 48.81,70.919 49.093,71.201 49.093,71.614 U5.2@49.095,71.616 ; R12.2@47.658,70.057 R12.2@47.671,70.07
NetR13_2: R13.2 U6.3 | length 2.6
  Top Layer w0.254: R13.2@87.08,59.144 87.253,59.317 87.253,59.643 88.171,60.562 U6.3@88.171,61.325
NetR14_2: R14.2 U7.3 | length 1.9
  Top Layer w0.254: R14.2@67.565,59.38 67.68,59.495 67.68,59.839 68.373,60.532 U7.3@68.373,60.964
NetR15_2: R15.2 U8.3 | length 2.2
  Top Layer w0.254: R15.2@49.046,59.2 49.073,59.227 49.073,59.895 49.484,60.306 49.484,60.787 U8.3@49.484,61.187
NetR25_1: R25.1 R26.1 R27.1 R28.1 R29.1 R30.1 R31.1 R32.1 R33.1 R34.1 R35.1 R36.1 R37.1 R38.1 R39.1 R40.2 R41.2 R42.2 R43.2 R44.2 | length 240.8
  Top Layer w0.254: R38.1@34.613,36.956 34.638,36.956 34.986,36.608 34.986,36.583 35.212,36.357 45.183,36.357 46.793,34.747 80.685,34.747 81.059,35.12 v1(81.105,35.12) ; R39.1@38.326,32.816 39.075,32.816 39.725,32.167 58.208,32.167 v1(58.225,32.184) ; R43.2@40.939,43.673 40.575,43.309 39.859,43.309 39.71,43.161 39.71,38.728 40.176,38.262 v1(41.335,38.262) ; R37.1@43.154,30.059 43.179,30.059 43.65,29.588 70.354,29.588 71.827,31.061 100.617,31.061 101.251,31.695 v1(101.261,31.695) ; R35.1@57.89,52.108 57.89,53.058 58.095,53.264 61.975,53.264 62.187,53.052 v1(62.187,52.658) ; R31.1@77.343,52.108 77.383,52.149 77.383,53.24 77.532,53.389 81.217,53.389 81.47,53.136 v1(81.537,53.136) ; R32.1@79.176,52.631 79.699,52.108 R32.1@79.974,52.108 ; R25.1@96.656,51.693 R25.1@96.656,52.108 96.656,53.058 96.978,53.38 100.823,53.38 101.249,52.954 v1(101.289,52.954)
  Signal Layer1 w0.254: v1(58.225,32.184) 58.255,32.214 58.457,32.214 62.187,35.944 v1(62.187,52.658) ; v1(81.105,35.12) 81.105,35.15 81.537,35.581 v1(81.537,53.136) ; v1(101.261,31.695) 101.275,31.709 101.275,52.94 v1(101.289,52.954)
  Bottom Layer w0.254: v1(41.335,38.262) 41.382,38.215 41.382,38.041 41.418,38.005 41.418,32.987 45.046,29.36 58.37,29.36 59.142,28.587 59.142,28.159 58.763,27.779 R40.2@58.763,27.679
  other v2: 43.622,39.807 42.616,39.847 43.622,40.607 42.611,40.99 43.622,41.407 42.626,42.076 43.622,42.207 43.622,43.007 42.624,43.309 43.622,43.807 42.619,44.452 43.622,44.607 43.622,45.407 42.634,45.539 43.622,46.207 42.616,46.648 43.622,47.007 42.611,47.791 43.622,47.807 51.825,47.994 52.825,47.994 53.825,47.994 54.825,47.994 55.825,47.994 56.825,47.994 57.825,47.994 58.825,47.994 59.825,47.994 60.825,47.994 71.206,47.997 72.206,47.997 73.206,47.997 74.206,47.997 75.206,47.997 76.206,47.997 77.206,47.997 78.206,47.997 79.206,47.997 80.206,47.997 90.645,47.989 91.645,47.989 92.645,47.989 93.645,47.989 94.645,47.989 95.645,47.989 96.645,47.989 97.645,47.989 98.645,47.989 99.645,47.989 43.622,48.607 51.825,48.794 52.825,48.794 53.825,48.794 54.825,48.794 55.825,48.794 56.825,48.794 57.825,48.794 58.825,48.794 59.825,48.794 60.825,48.794 71.206,48.797 72.206,48.797 73.206,48.797 74.206,48.797 75.206,48.797 76.206,48.797 77.206,48.797 78.206,48.797 79.206,48.797 80.206,48.797 90.645,48.789 91.645,48.789 92.645,48.789 93.645,48.789 94.645,48.789 95.645,48.789 96.645,48.789 97.645,48.789 98.645,48.789 99.645,48.789 42.626,48.877 43.622,49.407 51.825,49.594 52.825,49.594 53.825,49.594 54.825,49.594 55.825,49.594 56.825,49.594 57.825,49.594 58.825,49.594 59.825,49.594 60.825,49.594 71.206,49.597 72.206,49.597 73.206,49.597 74.206,49.597 75.206,49.597 76.206,49.597 77.206,49.597 78.206,49.597 79.206,49.597 80.206,49.597 90.645,49.589 91.645,49.589 92.645,49.589 93.645,49.589 94.645,49.589 95.645,49.589 96.645,49.589 97.645,49.589 98.645,49.589 99.645,49.589 42.593,50.2 43.622,50.207 51.825,50.394 52.825,50.394 53.825,50.394 54.825,50.394 55.825,50.394 56.825,50.394 57.825,50.394 58.825,50.394 59.825,50.394 60.825,50.394 71.206,50.397 72.206,50.397 73.206,50.397 74.206,50.397 75.206,50.397 76.206,50.397 77.206,50.397 78.206,50.397 79.206,50.397 80.206,50.397 90.645,50.389 91.645,50.389 92.645,50.389 93.645,50.389 94.645,50.389 95.645,50.389 96.645,50.389 97.645,50.389 98.645,50.389 99.645,50.389 41.693,50.675 42.628,51.111 43.656,51.111
NetR46_1: R46.1 R50.2 U9.3 | length 12.6
  Top Layer w0.254: R50.2@17.232,30.542 17.382,30.392 U9.3@20.501,30.392 21.762,30.392 21.911,30.541 21.911,36.107 22.06,36.255 R46.1@24.12,36.255
NetR56_2: R56.2 U10.3 | length 1.4
  Bottom Layer w0.254: U10.3@58.036,19.674 58.108,19.747 R56.2@58.108,21.07
NetR57_1: R57.1 R60.2 U9.5 | length 12.5
  Top Layer w0.254: R60.2@17.307,28.942 17.457,29.092 U9.5@20.501,29.092 22.82,29.092 22.969,29.241 22.969,34.735 23.118,34.884 R57.1@24.132,34.884
NetR63_1: R63.1 R64.2 U9.10 | length 8.6
  Top Layer w0.254: R63.1@24.115,33.294 24.115,29.689 24.712,29.092 U9.10@26.101,29.092 27.466,29.092 27.803,29.429 R64.2@28.684,29.429
NetR65_1: R65.1 R70.2 U11.3 | length 5.4
  Bottom Layer w0.254: U11.3@67.49,9.587 68.275,9.587 68.786,10.097 68.786,11.846 ; R70.2@67.549,11.846 68.786,11.846 ; R65.1@69.727,11.846 68.786,11.846
NetR66_1: R66.1 R69.1 U11.1 | length 4.9
  Bottom Layer w0.254: R69.1@67.395,6.606 67.459,6.669 68.086,6.669 68.3,6.456 68.3,5.13 68.448,4.981 69.276,4.981 R66.1@69.301,5.006 ; R69.1@67.395,6.823 67.49,6.918 U11.1@67.49,8.287
NetR79_1: R79.1 U9.13 U9.14 | length 4.2
  Top Layer w0.254: U9.13@26.101,31.042 U9.14@26.101,31.692 27.162,31.692 27.453,31.982 27.453,32.708 27.601,32.857 28.434,32.857 R79.1@28.651,32.639
OCP: C115.1 J3.13 R69.2 | length 15.6
  Bottom Layer w0.254: C115.1@67.395,3.253 67.395,3.464 R69.2@67.395,5.223 ; C115.1@67.395,3.258 73.009,3.258 74.156,4.405 74.156,8.438 J3.13@75.819,10.101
